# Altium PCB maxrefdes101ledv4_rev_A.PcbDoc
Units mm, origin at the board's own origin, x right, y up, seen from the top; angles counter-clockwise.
Board outline 6.76 x 10.36 mm, 2 copper layers (Top Layer, Bottom Layer), stack 0.569 mm thick; 3 components, 6 nets, 29 pads, 2 vias.
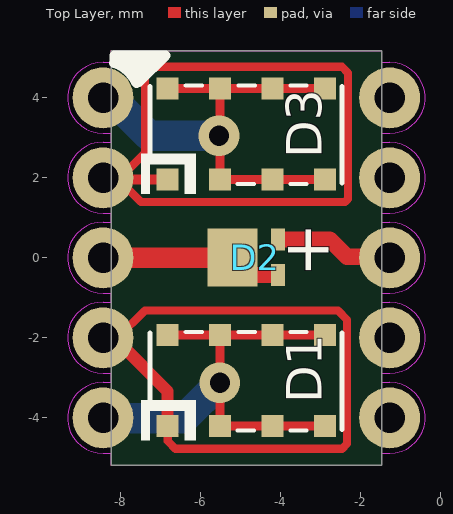
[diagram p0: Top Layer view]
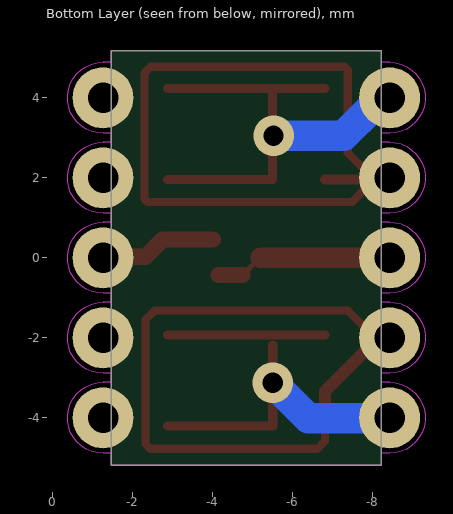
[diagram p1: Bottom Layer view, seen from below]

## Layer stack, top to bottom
Top Solder: solder mask 0.0102, Solder Resist, Dk 3.5
Top Layer: signal copper 0.0347
Dielectric1: core 0.5, FR-4, Dk 4.2
Bottom Layer: signal copper 0.0347
Bottom Solder: solder mask 0.0102, Solder Resist, Dk 3.5

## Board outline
-8.23,-5.182 -1.473,-5.182 -1.473,5.182 -8.23,5.182

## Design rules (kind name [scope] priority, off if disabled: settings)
Clearance Clearance_2 [InNamedPolygon('COMPONENT_GND')] p1: gap=0.279 ignorepadtopadclearanceinfootprint=FALSE except(0: Arc-Hole Track-Hole SMDPad-Hole THPad-Hole Via-Hole Fill-Hole Poly-Hole Region-Hole Text-Hole)
Clearance Clearance_1 [InNamedPolygon('PLANE_5V')] p2: gap=0.203 ignorepadtopadclearanceinfootprint=FALSE except(0: Arc-Hole Track-Hole SMDPad-Hole THPad-Hole Via-Hole Fill-Hole Poly-Hole Region-Hole Text-Hole)
Clearance Clearance_PD_Shield [InNamedPolygon('PLANE_1V8')] p3: gap=0.152 ignorepadtopadclearanceinfootprint=FALSE except(0: Arc-Hole Track-Hole SMDPad-Hole THPad-Hole Via-Hole Fill-Hole Poly-Hole Region-Hole Text-Hole)
Clearance "Clearance_Bottom Layer" [OnLayer('Bottom Layer')] p4: gap=0.127 ignorepadtopadclearanceinfootprint=FALSE except(0: Arc-Hole Track-Hole SMDPad-Hole THPad-Hole Via-Hole Fill-Hole Poly-Hole Region-Hole Text-Hole)
Clearance "Clearance Power Plane" [OnLayer('Power Plane 1.8v')] p5: gap=0.127 ignorepadtopadclearanceinfootprint=FALSE except(0: Arc-Hole Track-Hole SMDPad-Hole THPad-Hole Via-Hole Fill-Hole Poly-Hole Region-Hole Text-Hole)
Clearance "Clearance Ground Plane" [(OnLayer('Ground Plane +') AND InNamedPolygon('GND'))] p6: gap=0.127 ignorepadtopadclearanceinfootprint=FALSE except(0: Arc-Hole Track-Hole SMDPad-Hole THPad-Hole Via-Hole Fill-Hole Poly-Hole Region-Hole Text-Hole)
Clearance [All] p7: gap=0.076 ignorepadtopadclearanceinfootprint=FALSE except(0: Arc-Hole Track-Hole SMDPad-Hole THPad-Hole Via-Hole Fill-Hole Poly-Hole Region-Hole Text-Hole)
ComponentClearance [All] p1: gap=0 collisioncheckmode=3 verticalgap=0 showdistances=FALSE
HoleSize [All] p1: absolutevalues=TRUE maxlimit=12.7 minlimit=0.102 maxpercent=80.000 minpercent=20.000
HoleToHoleClearance [All] p1: gap=0.229 allowstackedmicrovias=TRUE
MinimumAnnularRing [All] p1: minimumring=0.051
MinimumSolderMaskSliver [All] p1: minsoldermaskwidth=0
PlaneConnect [All] p1: planeconnectstyle=Relief reliefexpansion=0.508 reliefentries=4 reliefconductorwidth=0.178 reliefairgap=0.254
PolygonConnect PolygonConnect_5 [All vs IsNamedPolygon('PLANE_5V')] p1: connectstyle=Relief reliefconductorwidth=0.254 reliefentries=4 polygonreliefangle="90 Angle" airgapwidth=0.33
PolygonConnect PolygonConnect_4 [All vs IsNamedPolygon('PLANE_GROUND')] p2: connectstyle=Relief reliefconductorwidth=0.203 reliefentries=4 polygonreliefangle="90 Angle" airgapwidth=0.229
PolygonConnect PolygonConnect_3 [All vs IsNamedPolygon('PP_5V')] p3: connectstyle=Relief reliefconductorwidth=0.356 reliefentries=4 polygonreliefangle="90 Angle" airgapwidth=0.254
PolygonConnect PolygonConnect_2 [All vs IsNamedPolygon('PP_1V8')] p4: connectstyle=Relief reliefconductorwidth=0.254 reliefentries=4 polygonreliefangle="90 Angle" airgapwidth=0.203
PolygonConnect PolygonConnect_1 [All vs IsNamedPolygon('PLANE_1V8')] p5: connectstyle=Relief reliefconductorwidth=0.279 reliefentries=4 polygonreliefangle="45 Angle" airgapwidth=0.254
PolygonConnect [All] p6: connectstyle=Relief reliefconductorwidth=0.127 reliefentries=4 polygonreliefangle="45 Angle" airgapwidth=0.254
RoutingVias [All] p1: holewidth=0.203 width=0.406 viastyle="Through Hole" minholewidth=0.102 minwidth=0.203 maxholewidth=0.711 maxwidth=1.27
SilkToSilkClearance [All] p1: silktosilkclearance=0
SilkToSolderMaskClearance SilkscreenOverComponentPads [IsPad] p1: minsilkscreentomaskgap=0.102 clearancetoexposedcopper=TRUE
SolderMaskExpansion [All] p1: expansion=0.102
Width [All] p1: maxlimit=2.54 minlimit=0.076 preferedwidth=0.127 minimp=50.000000 maximp=50.000000 favimp=50.000000
23 further rules are at their usual default settings.

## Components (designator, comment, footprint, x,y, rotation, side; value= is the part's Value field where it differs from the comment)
D1 "VEMD8080" PHOTODIODE_VEMD8080 -2.89,-1.88 r180 top
D2 "FIREFLY E2218" LED_FIREFLY_E2218 -4.064,-0.432 r180 top
D3 "VEMD8080" PHOTODIODE_VEMD8080 -2.89,4.286 r180 top (schematic designator D4)

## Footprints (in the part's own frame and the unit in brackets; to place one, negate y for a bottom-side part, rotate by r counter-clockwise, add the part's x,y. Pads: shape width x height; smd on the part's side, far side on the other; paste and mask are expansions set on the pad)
LED_FIREFLY_E2218 [mm] "OSRAM FIREFLY E2218 LED"
  rect 0.35x0.55 smd: 1(0,0) 2(0,-0.89)
  rect 1.25x1.45 smd: 1(1.143,-0.445)
  body extent -0.32,-1.33 1.89,0.47, height 0.61
PHOTODIODE_VEMD8080 [mm] "Vishay Photodiode VEMD8080"
  rect 0.55x0.55 smd: 1(0,2.329) 1(0,0.051) 1(1.31,2.329) 1(1.31,0.051) 1(2.62,2.329) 1(2.62,0.051) 1(3.93,0.051) 2(3.93,2.329)
  silkscreen extent -0.43,-0.03 4.6,2.69, body extent -0.43,-0.05 4.39,2.45, height 0.48

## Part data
D1 D3: library part PHOTODIODE_VEMD8080, "Silicon PIN Photodiode"
D2: library part LED_FIREFLYE2218, "OSRAM WHRM SMD LED Vf+2.3V"

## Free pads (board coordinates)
  round 1.524 hole 0.762: 1(-8.438,-4) 1(-8.438,-2) 1(-8.438,0) 1(-8.438,2) 1(-8.438,4) 1(-1.273,-4) 1(-1.273,-2) 1(-1.273,0) 1(-1.273,2) 1(-1.273,4)

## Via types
v1: diameter 1.016, hole 0.508, Top Layer to Bottom Layer, tented bottom, 2 vias

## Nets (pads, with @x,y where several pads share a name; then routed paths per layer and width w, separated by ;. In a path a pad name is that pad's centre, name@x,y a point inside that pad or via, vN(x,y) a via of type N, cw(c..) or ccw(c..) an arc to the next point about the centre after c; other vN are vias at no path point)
LED1_C: D2.1 pad.1@-8.438,0 | length 4.5
  Top Layer w0.127: D2.1@-5.22,0 -5.207,0.013 D2.1@-4.762,-0.432
  Top Layer w0.406: D2.1@-4.762,-0.432 D2.1@-4.166,-0.432
  Top Layer w0.508: pad.1@-8.438,0 D2.1@-5.22,0
PD1_A: D1.2 pad.1@-8.438,-2 | length 17.2
  Top Layer w0.127: pad.1@-8.438,-2 -8.238,-2 pad.1@-8.071,-2 ; pad.1@-8.238,-2.083 pad.1@-8.077,-2.083
  Top Layer w0.203: pad.1@-8.071,-2 -7.391,-1.321 -2.565,-1.321 -2.337,-1.549 -2.337,-4.648 -2.464,-4.775 -6.629,-4.775 -6.82,-4.585 D1.2
  Top Layer w0.305: pad.1@-8.077,-2.083 -6.826,-3.334 D1.2@-6.826,-3.962
  Top Layer w0.508: pad.1@-8.238,-2.083 pad.1@-8.238,-2
PD1_C: D1.1 pad.1@-8.438,-4 | length 11.6
  Top Layer w0.229: D1.1@-6.82,-1.931 -5.51,-1.931 -4.2,-1.931 D1.1@-2.89,-1.931 ; D1.1@-5.516,-4.209 v1(-5.516,-3.124) D1.1@-5.516,-2.184 ; D1.1@-5.51,-4.209 -4.2,-4.209 D1.1@-2.89,-4.209
  Bottom Layer w0.762: pad.1@-8.204,-4.013 -6.405,-4.013 v1(-5.516,-3.124)
PD2_A: D3.2 pad.1@-8.438,2 | length 19
  Top Layer w0.127: pad.1@-8.438,2 -8.096,2 pad.1@-8.053,1.957
  Top Layer w0.203: pad.1@-8.053,1.957 -7.391,2.618 -7.391,4.699 -7.315,4.775 -2.464,4.775 -2.311,4.623 -2.311,1.473 -2.388,1.397 -7.493,1.397 pad.1@-8.053,1.957
  Top Layer w0.254: pad.1@-8.053,1.957 D3.2
PD2_C: D3.1 pad.1@-8.438,4 | length 11.9
  Top Layer w0.229: D3.1@-6.82,4.235 D3.1@-5.51,4.235 ; D3.1@-2.89,1.957 -4.2,1.957 -5.51,1.957 D3.1@-5.51,4.235 ; D3.1@-2.89,4.235 -4.2,4.235 D3.1@-5.51,4.235
  Bottom Layer w0.127: pad.1@-8.238,4 pad.1@-7.997,3.759
  Bottom Layer w0.762: pad.1@-7.997,3.759 -7.286,3.048 v1(-5.537,3.048)
VLED: D2.2 pad.1@-1.273,0 | length 2.9
  Top Layer w0.406: D2.2@-4.013,0.457 -2.769,0.457 -2.337,0.025 pad.1@-1.273,0.025

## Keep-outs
Keep-Out Layer:
  lines w0.025: -8.438,-2.884 cw(c-8.438,-1.995) -8.438,-1.106 -8.238,-1.106 ; -8.438,0.894 ccw(c-8.438,0.005) -8.438,-0.884 -8.238,-0.884 -8.238,-1.106 ; -8.438,1.116 cw(c-8.438,2.005) -8.438,2.894 ; -8.43,-2.884 -8.238,-2.884 -8.238,-3.111 ; -8.43,0.894 -8.238,0.894 -8.238,1.116 -8.43,1.116 ; -8.43,2.894 -8.238,2.894 -8.238,3.111 ; -8.238,-4.889 -8.238,-5.182 -1.473,-5.182 -1.473,-4.889 -1.273,-4.889 ccw(c-1.273,-4) -1.273,-3.111 -1.473,-3.111 -1.473,-2.889 -1.273,-2.889 ccw(c-1.273,-2) -1.273,-1.111 -1.473,-1.111 -1.473,-0.889 -1.273,-0.889 ccw(c-1.273,0) -1.273,0.889 -1.473,0.889 -1.473,1.111 -1.273,1.111 ccw(c-1.273,2) -1.273,2.889 -1.473,2.889 -1.473,3.111 -1.273,3.111 ccw(c-1.273,4) -1.273,4.889 -1.473,4.889 -1.473,5.182 -8.238,5.182 -8.238,4.889 ; -8.238,-4.889 -8.438,-4.889 cw(c-8.438,-4) -8.438,-3.111 -8.238,-3.111 ; -8.238,3.111 -8.438,3.111 cw(c-8.438,4) -8.438,4.889 -8.238,4.889

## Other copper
Top Layer:
  text "Top Layer" at 12.522,2.718 h1.52
Bottom Layer:
  text "Bottom Layer" at 12.243,-2.616 h1.52

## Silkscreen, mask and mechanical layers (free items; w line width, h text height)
Top Overlay:
  lines w0.254: -8.156,4.87 cw(c-8.438,4) -7.601,4.369 ; -8.153,4.877 -8.128,4.902 -7.214,4.902 -7.188,4.877 -7.366,4.699 -7.747,4.699 ; -8.153,4.877 -7.925,4.877 -7.747,4.699 ; -8.153,4.877 -8.153,5.055 -6.883,5.055 -7.544,4.394 -7.544,4.47 -7.747,4.674 -7.747,4.699
  text "Top Silkscreen" at 12.243,6.223 h1.52
  text "+" at -2.413,-0.483 h2.03 r90
Bottom Overlay:
  text "Bottom Silkscreen" at 12.446,-5.309 h1.52
Mechanical 11:
  the board outline again, w0.025
  text "Board Outline" at 12.471,-7.595 h1.52
Mechanical 16:
  circle w0.635: c195.902,-2.517 r4.016
  lines w0.127: -35.687,29.083 -30.607,29.083 ; -35.484,95.504 -30.404,95.504 ; -35.484,155.829 -30.404,155.829 ; 27.813,-31.242 27.813,-26.162 ; 27.813,204.978 27.813,210.058 ; 91.313,-31.242 91.313,-26.162 ; 91.313,204.978 91.313,210.058 ; 154.813,-31.242 154.813,-26.162 ; 154.813,204.978 154.813,210.058 ; 218.313,-31.242 218.313,-26.162 ; 218.313,204.978 218.313,210.058 ; 225.933,-18.542 340.233,-18.542 ; 225.933,-10.922 340.233,-10.922 ; 225.933,-3.302 264.033,-3.302 ; 264.033,-26.162 264.033,-10.922 264.033,4.318 ; 281.813,-31.242 281.813,-26.162 ; 281.813,204.978 281.813,210.058 ; 317.373,-26.162 317.373,-10.922 ; 340.233,29.083 345.313,29.083 ; 340.233,89.408 345.313,89.408 ; 340.233,149.733 345.313,149.733 ; 225.933,-26.162 225.933,4.318 ; 225.933,-26.162 340.233,-26.162 ; 225.933,-26.162 190.373,-26.162 190.373,4.318 225.933,4.318 ; 225.933,4.318 264.033,4.318 ; 264.033,4.318 340.233,4.318 340.233,-26.162 ; 340.233,-26.162 -30.607,-26.162 -30.607,204.978 340.233,204.978 340.233,-26.162 ; -35.687,-31.242 345.313,-31.242 345.313,210.058 -35.687,210.058 -35.687,-31.242
  text "1" at -4.411,206.756 h1.78
  text "2" at 58.979,206.756 h1.78
  text "3" at 122.208,206.756 h1.78
  text "4" at 185.877,206.756 h1.78
  text "5" at 249.352,206.756 h1.78
  text "6" at 312.979,206.756 h1.78
  text "A" at -33.782,177.724 h1.78
  text "A" at 342.138,177.724 h1.78
  text "B" at -33.579,123.368 h1.78
  text "B" at 342.138,117.272 h1.78
  text "C" at -33.782,56.947 h1.78
  text "C" at 342.138,56.947 h1.78
  text "ENGINEER:" at 227.203,1.778 h1.14
  text "TITLE:" at 265.303,1.778 h1.14
  text "maxim" at 201.363,-1.582 h5.71
  text "maxrefdes101ledv4" at 267.818,-2.032 h3
  text "D" at -33.782,-3.251 h1.78
  text "D" at 342.138,-3.251 h1.78
  text "T" at 221.429,-5.392 h2.54
  text "M" at 222.699,-5.392 h2.54
  text "integrated" at 201.363,-5.646 h5.71
  text "PCB DESIGNER:" at 227.203,-5.715 h1.14
  text "Maxim Integrated" at 193.108,-11.107 h2.03
  text "DATE:" at 227.203,-13.462 h1.14
  text "PART NO.:" at 265.303,-13.462 h1.14
  text "REV:" at 318.643,-13.462 h1.14
  text "160 Rio Robles" at 193.108,-15.044 h2.03
  text "A" at 323.113,-16.078 h1.5
  text "4/5/2018" at 227.99,-16.434 h1.5
  text "San Jose, CA 95134" at 193.108,-17.965 h2.03
  text "FILE NAME:" at 227.203,-21.082 h1.14
  text "DWG NO:" at 265.303,-21.082 h1.14
  text "SCALE:" at 318.643,-21.082 h1.14
  text "(408) 733-7600" at 192.981,-21.648 h2.03
  text "maxrefdes101ledv4" at 228.473,-24.13 h1.5
  text "1" at -4.411,-29.464 h1.78
  text "2" at 58.979,-29.464 h1.78
  text "3" at 122.208,-29.464 h1.78
  text "4" at 185.877,-29.464 h1.78
  text "5" at 249.352,-29.464 h1.78
  text "6" at 312.979,-29.464 h1.78
Drill Drawing:
  circle w0.254: c62.629,85.708 r0.508
  circle w0.254: c62.629,85.708 r0.847
  lines w0.254: 61.782,90.365 63.476,90.365 62.629,88.671 61.782,90.365 ; 62.121,90.026 63.137,90.026 62.629,89.01 62.121,90.026
  lines w0.381: 60.264,83.718 326.737,83.718 ; 60.264,91.338 326.737,91.338 ; 74.256,79.908 74.256,95.148 ; 87.714,79.908 87.714,95.148 ; 115.646,79.908 115.646,95.148 ; 128.495,79.908 128.495,95.148 ; 147.134,79.908 147.134,95.148 ; 185.223,79.908 185.223,95.148 ; 200.205,79.908 200.205,95.148 ; 219.148,79.908 219.148,95.148 ; 236.161,79.908 236.161,95.148 ; 257.847,79.908 257.847,95.148 ; 291.721,79.908 291.721,95.148 ; 60.264,79.908 326.737,79.908 326.737,95.148 60.264,95.148 60.264,79.908
  text "Symbol" at 62.55,92.481 h1.83
  text "Count" at 75.399,92.481 h1.83
  text "Hole Size" at 88.857,92.481 h1.83
  text "Plated" at 116.789,92.481 h1.83
  text "Hole Type" at 129.638,92.481 h1.83
  text "Drill Layer Pair" at 148.277,92.481 h1.83
  text "Via/Pad" at 186.366,92.481 h1.83
  text "Pad Shape" at 201.348,92.481 h1.83
  text "Template" at 220.291,92.481 h1.83
  text "Description" at 237.304,92.481 h1.83
  text "Hole Tolerance (+)" at 258.99,92.481 h1.83
  text "Hole Tolerance (-)" at 292.864,92.481 h1.83
  text "2" at 75.399,88.671 h1.52
  text "0.508mm (20.00mil)" at 88.857,88.671 h1.52
  text "PTH" at 116.789,88.671 h1.52
  text "Round" at 129.638,88.671 h1.52
  text "Top Layer - Bottom Layer" at 148.277,88.671 h1.52
  text "Via" at 186.366,88.671 h1.52
  text "Rounded" at 201.348,88.671 h1.52
  text "v102h51mx0" at 220.291,88.671 h1.52
  text "10" at 75.399,84.861 h1.52
  text "0.762mm (30.00mil)" at 88.857,84.861 h1.52
  text "PTH" at 116.789,84.861 h1.52
  text "Round" at 129.638,84.861 h1.52
  text "Top Layer - Bottom Layer" at 148.277,84.861 h1.52
  text "Pad" at 186.366,84.861 h1.52
  text "Rounded" at 201.348,84.861 h1.52
  text "c152h76" at 220.291,84.861 h1.52
  text "12 Total" at 75.399,81.051 h1.52
Mechanical 31:
  drawing of 203 lines, arcs and shapes, not listed
  text "NOTES" at -25.324,193.015 h5
  text "ALL MEASUREMENTS ARE IN INCHES /  / BOARD MATERIAL TO BE MULTI FUNCTIONAL FR4 EPOXY GLASS / LAMINATE AND SHALL MEET OR EXCEED MIL-P-13949 COLOR - NATURAL /  / OVERALL BOARD THICKNESS TO BE 0.6mm +/-10 MEASURED FROM COPPER TO COPPER" at -21.336,158.318 h5
  text "PROCESS NOTES" at -25.832,144.831 h5
  text "APPLY SOLDERMASK. BOTH SIDES. OVER BARE COPPER (SMOBC) /  / COLOR : MATTE BLACK /  / SOLDERMASK SHALL CONFORM IPC-SM-840. CLASS H / FABRICATION VENDOR IS ALLOWED TO ADJUST SOLDERMASK FEATURES AS NEEDED AS LONG AS SOLDERMAK / DAMS ARE MAINTAINED  BETWEEN ALL SMD PADS" at -21.844,106.324 h5
  text "Layer" at 81.822,73.508 h1.52
  text "Name" at 92.234,73.508 h1.52
  text "Material" at 115.849,73.508 h1.52
  text "Thickness" at 137.687,73.508 h1.52
  text "Constant" at 154.193,73.508 h1.52
  text "Board Layer Stack" at 168.668,73.508 h1.52
  text "1" at 81.822,70.46 h1.52
  text "Top Overlay" at 92.234,70.46 h1.52
  text "2" at 81.822,67.412 h1.52
  text "Top Solder" at 92.234,67.412 h1.52
  text "Solder Resist" at 115.849,67.412 h1.52
  text "0.40mil" at 137.687,67.412 h1.52
  text "3.5" at 154.193,67.412 h1.52
  text "0.6mm FR4 /  / 2 LAYERS /  / MATTE BLACK SOLDERMASK /  / CASTALLATED VIAS ON BOTH EDGES /  / ENIG Surface Finish" at -21.742,66.65 h5
  text "3" at 81.822,64.364 h1.52
  text "Top Layer" at 92.234,64.364 h1.52
  text "Copper" at 115.849,64.364 h1.52
  text "1.37mil" at 137.687,64.364 h1.52
  text "4" at 81.822,61.316 h1.52
  text "Dielectric1" at 92.234,61.316 h1.52
  text "FR-4" at 115.849,61.316 h1.52
  text "19.69mil" at 137.687,61.316 h1.52
  text "4.2" at 154.193,61.316 h1.52
  text "5" at 81.822,58.268 h1.52
  text "Bottom Layer" at 92.234,58.268 h1.52
  text "Copper" at 115.849,58.268 h1.52
  text "1.37mil" at 137.687,58.268 h1.52
  text "6" at 81.822,55.22 h1.52
  text "Bottom Solder" at 92.234,55.22 h1.52
  text "Solder Resist" at 115.849,55.22 h1.52
  text "0.40mil" at 137.687,55.22 h1.52
  text "3.5" at 154.193,55.22 h1.52
  text "7" at 81.822,52.172 h1.52
  text "Bottom Overlay" at 92.234,52.172 h1.52
  text "10x Castallated Vias  (Cut Vias)" at 5.918,15.164 h1.52
  text "Soldermask For Top Layer : .MATTE BLACK" at 34.62,3.398 h1.52
  text "Soldermask For Bottom Layer : MATTE BLACK" at 34.722,-3.048 h1.52
  text "Notes" at 12.421,-10.363 h1.52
